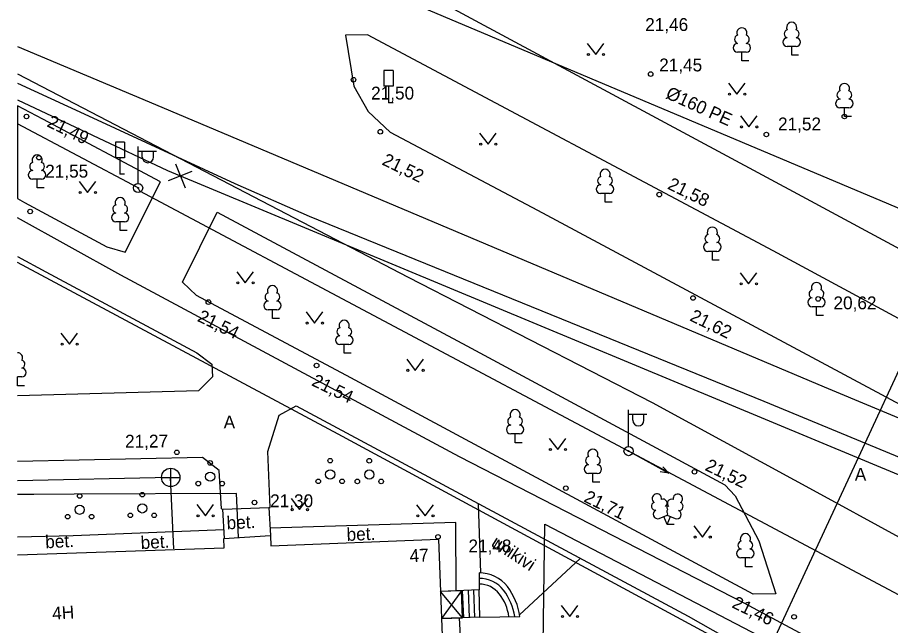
# Model space of a CAD drawing. Extents: x 714038 to 714279, y 6589845 to 6590041.
# Drawn here: x 714037.81 to 714085.35, y 6589987.55 to 6590020.65 of the extents above; entities that cross this region are included whole.
import ezdxf

# ---------------------------------------------------------------- set-up
doc = ezdxf.new("R2010")
doc.units = 0
for name, color, linetype in [('HALJASTUS', 7, 'Continuous'), ('HOONE', 7, 'Continuous'), ('HOONEDET', 7, 'Continuous'), ('KKAEV', 7, 'Continuous'), ('KORGUS', 7, 'Continuous'), ('KTRASS', 7, 'Continuous'), ('LIIKLUS', 7, 'Continuous'), ('MPKAABEL', 7, 'Continuous'), ('MPOHULIIN', 7, 'Continuous'), ('POST', 7, 'Continuous'), ('PUU', 7, 'Continuous'), ('SITRASS', 7, 'Continuous'), ('TEE', 7, 'Continuous'), ('VTRASS', 7, 'Continuous'), ('Слой 1', 7, 'Continuous')]:
    doc.layers.add(name, color=color, linetype=linetype)

msp = doc.modelspace()

# ---------------------------------------------------------------- linework, layer by layer
at = {"layer": 'HALJASTUS'}
for p, q in [((714068.837, 6590019.239), (714069.3, 6590018.632)), ((714069.3, 6590018.632), (714069.746, 6590019.239)), ((714076.527, 6590017.077), (714076.99, 6590016.47)), ((714076.99, 6590016.47), (714077.436, 6590017.077)), ((714077.18, 6590015.297), (714077.643, 6590014.691)), ((714077.643, 6590014.691), (714078.089, 6590015.297)), ((714062.973, 6590014.359), (714063.437, 6590013.753)), ((714063.437, 6590013.753), (714063.882, 6590014.359)), ((714041.166, 6590011.73), (714041.629, 6590011.124)), ((714041.629, 6590011.124), (714042.075, 6590011.73)), ((714049.75, 6590006.812), (714050.214, 6590006.205)), ((714050.214, 6590006.205), (714050.659, 6590006.812)), ((714077.159, 6590006.756), (714077.623, 6590006.149)), ((714077.623, 6590006.149), (714078.068, 6590006.756)), ((714053.525, 6590004.626), (714053.989, 6590004.019)), ((714053.989, 6590004.019), (714054.434, 6590004.626)), ((714040.176, 6590003.473), (714040.64, 6590002.866)), ((714040.64, 6590002.866), (714041.085, 6590003.473)), ((714059.008, 6590002.051), (714059.471, 6590001.444)), ((714059.471, 6590001.444), (714059.917, 6590002.051)), ((714066.767, 6589997.739), (714067.231, 6589997.132)), ((714067.231, 6589997.132), (714067.676, 6589997.739)), ((714052.711, 6589994.467), (714053.174, 6589993.861)), ((714053.174, 6589993.861), (714053.62, 6589994.467)), ((714047.581, 6589994.138), (714048.044, 6589993.531)), ((714048.044, 6589993.531), (714048.49, 6589994.138)), ((714059.548, 6589994.127), (714060.011, 6589993.52)), ((714060.011, 6589993.52), (714060.457, 6589994.127)), ((714074.646, 6589992.978), (714075.11, 6589992.371)), ((714075.11, 6589992.371), (714075.555, 6589992.978)), ((714067.421, 6589988.652), (714067.885, 6589988.046)), ((714067.885, 6589988.046), (714068.33, 6589988.652))]:
    msp.add_line(p, q, dxfattribs=at)
for centre, radius in [((714068.899, 6590018.632), 0.055), ((714069.728, 6590018.632), 0.055), ((714076.589, 6590016.47), 0.055), ((714077.418, 6590016.47), 0.055), ((714077.242, 6590014.691), 0.055), ((714078.071, 6590014.691), 0.055), ((714063.036, 6590013.753), 0.055), ((714063.864, 6590013.753), 0.055), ((714041.228, 6590011.124), 0.055), ((714042.057, 6590011.124), 0.055), ((714049.813, 6590006.205), 0.055), ((714050.642, 6590006.205), 0.055), ((714077.222, 6590006.149), 0.055), ((714078.051, 6590006.149), 0.055), ((714053.588, 6590004.019), 0.055), ((714054.416, 6590004.019), 0.055), ((714040.239, 6590002.866), 0.055), ((714041.068, 6590002.866), 0.055), ((714059.07, 6590001.444), 0.055), ((714059.899, 6590001.444), 0.055), ((714066.83, 6589997.132), 0.055), ((714067.658, 6589997.132), 0.055), ((714048.306, 6589996.404), 0.125), ((714054.839, 6589996.528), 0.125), ((714056.968, 6589996.522), 0.125), ((714048.306, 6589995.654), 0.25), ((714054.839, 6589995.778), 0.25), ((714056.968, 6589995.772), 0.25), ((714047.656, 6589995.279), 0.125), ((714048.956, 6589995.279), 0.125), ((714054.189, 6589995.403), 0.125), ((714055.489, 6589995.403), 0.125), ((714056.318, 6589995.397), 0.125), ((714057.618, 6589995.397), 0.125), ((714044.607, 6589994.679), 0.125), ((714041.196, 6589994.606), 0.125), ((714041.196, 6589993.856), 0.25), ((714044.607, 6589993.929), 0.25), ((714052.773, 6589993.861), 0.055), ((714053.602, 6589993.861), 0.055), ((714040.546, 6589993.481), 0.125), ((714041.846, 6589993.481), 0.125), ((714043.957, 6589993.554), 0.125), ((714045.257, 6589993.554), 0.125), ((714047.643, 6589993.531), 0.055), ((714048.472, 6589993.531), 0.055), ((714059.61, 6589993.52), 0.055), ((714060.439, 6589993.52), 0.055), ((714074.709, 6589992.371), 0.055), ((714075.538, 6589992.371), 0.055), ((714067.484, 6589988.046), 0.055), ((714068.312, 6589988.046), 0.055)]:
    msp.add_circle(centre, radius, dxfattribs=at)
at = {"layer": 'HOONE'}
for points in [[(714037.81, 6590017.576), (714059.08, 6590006.51), (714072.38, 6589999.69), (714082.14, 6589994.37), (714104.85, 6589981.96), (714150.21, 6589957.43), (714183.55, 6589939.45), (714202.68, 6589928.99), (714214.04, 6589922.75), (714222.92, 6589918.06), (714237.47, 6589910.29), (714252.27, 6589902.23), (714256.602, 6589899.815), (714258.577, 6589898.715), (714261.69, 6589896.98)], [(714049.84, 6589992.36), (714049.74, 6589994.74), (714040.901, 6589994.702), (714038.703, 6589994.692), (714037.81, 6589994.688)], [(714049.068, 6589991.791), (714049.048, 6589992.294), (714051.589, 6589992.446), (714051.611, 6589991.89), (714060.739, 6589992.247), (714061.143, 6589981.755), (714037.81, 6589980.739)], [(714037.81, 6589991.404), (714049.068, 6589991.791)], [(714060.905, 6589987.935), (714062.038, 6589987.979), (714061.984, 6589989.451), (714060.848, 6589989.407)], [(714062.038, 6589987.979), (714060.848, 6589989.407)], [(714061.984, 6589989.451), (714060.905, 6589987.935)]]:
    msp.add_lwpolyline(points, dxfattribs=at)
at = {"layer": 'HOONEDET'}
for p, q in [((714062.946, 6589990.419), (714062.947, 6589989.494)), ((714062.947, 6589989.494), (714060.848, 6589989.413)), ((714062.035, 6589989.459), (714062.092, 6589987.975)), ((714062.353, 6589989.471), (714062.411, 6589987.988)), ((714062.638, 6589989.482), (714062.696, 6589987.999)), ((714062.993, 6589988.01), (714062.947, 6589989.494)), ((714062.993, 6589988.01), (714060.905, 6589987.93)), ((714062.993, 6589988.01), (714065.167, 6589988.045))]:
    msp.add_line(p, q, dxfattribs=at)
for points in [[(714037.81, 6589992.387), (714040.847, 6589992.447), (714049.055, 6589992.781)], [(714061.859, 6589987.966), (714062.226, 6589981.203), (714052.13, 6589980.7)]]:
    msp.add_lwpolyline(points, dxfattribs=at)
for centre, radius, start, end in [((714062.981, 6589988.523), 1.897, 37.2498, 91.0776), ((714062.991, 6589988.505), 1.615, 36.7967, 91.5949), ((714062.943, 6589988.406), 1.409, 37.7811, 89.8581), ((714061.728, 6589987.57), 3.472, 7.8652, 37.2498), ((714062.053, 6589987.716), 2.536, 7.2366, 37.7811), ((714061.703, 6589987.542), 3.223, 8.8928, 36.7967)]:
    msp.add_arc(centre, radius, start, end, dxfattribs=at)
at = {"layer": 'KKAEV'}
for p, q in [((714046.154, 6589995.114), (714046.154, 6589996.114)), ((714045.654, 6589995.614), (714046.654, 6589995.614))]:
    msp.add_line(p, q, dxfattribs=at)
msp.add_circle((714046.154, 6589995.614), 0.5, dxfattribs=at)
at = {"layer": 'KORGUS'}
for centre in [(714072.29, 6590017.57), (714056.11, 6590017.26), (714038.3, 6590015.26), (714082.84, 6590015.26), (714057.57, 6590014.43), (714078.59, 6590014.28), (714038.98, 6590013.02), (714072.76, 6590011.01), (714038.5, 6590010.09), (714048.21, 6590005.16), (714074.6, 6590005.38), (714081.41, 6590005.33), (714054.1, 6590001.71), (714046.49, 6589996.98), (714074.68, 6589995.92), (714067.67, 6589995.03), (714050.72, 6589994.25), (714060.71, 6589992.38), (714080.1, 6589988.03)]:
    msp.add_circle(centre, 0.125, dxfattribs=at)
at = {"layer": 'KTRASS'}
for points in [[(714108.526, 6590000.746), (714093.581, 6590006.995), (714058.132, 6590021.931)], [(714046.149, 6589995.611), (714037.81, 6589995.433)], [(714046.319, 6589991.733), (714046.149, 6589995.611)]]:
    msp.add_lwpolyline(points, dxfattribs=at)
at = {"layer": 'LIIKLUS'}
for points in [[(714057.768, 6590017.762), (714057.768, 6590016.912)], [(714058.268, 6590017.762), (714057.768, 6590017.762)], [(714058.268, 6590017.762), (714058.268, 6590016.912)], [(714058.268, 6590016.912), (714057.768, 6590016.912)], [(714058.018, 6590016.912), (714058.018, 6590016.012)], [(714058.268, 6590016.012), (714058.018, 6590016.012)], [(714043.141, 6590013.869), (714043.141, 6590013.019)], [(714043.641, 6590013.869), (714043.141, 6590013.869)], [(714043.641, 6590013.869), (714043.641, 6590013.019)], [(714043.641, 6590013.019), (714043.141, 6590013.019)], [(714043.391, 6590013.019), (714043.391, 6590012.119)], [(714043.641, 6590012.119), (714043.391, 6590012.119)]]:
    msp.add_lwpolyline(points, dxfattribs=at)
at = {"layer": 'MPKAABEL'}
for p, q in [((714046.422, 6590012.681), (714046.935, 6590011.378)), ((714046.028, 6590011.773), (714047.33, 6590012.286))]:
    msp.add_line(p, q, dxfattribs=at)
for points in [[(714037.81, 6590016.164), (714045.98, 6590012.32), (714093.89, 6589992.4), (714122, 6589980.75)], [(714044.379, 6590011.372), (714037.81, 6590014.854)], [(714071.088, 6589997.05), (714044.469, 6590011.202), (714044.379, 6590011.372)], [(714097.447, 6589982.821), (714094.758, 6589984.46), (714071.268, 6589996.96), (714071.088, 6589997.05)]]:
    msp.add_lwpolyline(points, dxfattribs=at)
at = {"layer": 'MPOHULIIN'}
for p, q in [((714071.307, 6589996.929), (714073.275, 6589995.839)), ((714073.275, 6589995.839), (714072.953, 6589996.189)), ((714073.275, 6589995.839), (714072.808, 6589995.928))]:
    msp.add_line(p, q, dxfattribs=at)
at = {"layer": 'POST'}
for p, q in [((714044.379, 6590011.622), (714044.379, 6590013.622)), ((714044.379, 6590013.372), (714045.379, 6590013.372)), ((714044.606, 6590013.051), (714044.606, 6590013.372)), ((714045.218, 6590013.051), (714045.218, 6590013.372)), ((714071.088, 6589997.3), (714071.088, 6589999.3)), ((714071.088, 6589999.05), (714072.088, 6589999.05)), ((714071.315, 6589998.729), (714071.315, 6589999.05)), ((714071.928, 6589998.729), (714071.928, 6589999.05))]:
    msp.add_line(p, q, dxfattribs=at)
for centre, radius in [((714044.379, 6590011.372), 0.25), ((714044.379, 6590011.372), 0.0234), ((714071.088, 6589997.05), 0.25), ((714071.088, 6589997.05), 0.0234)]:
    msp.add_circle(centre, radius, dxfattribs=at)
for centre in [(714044.912, 6590013.051), (714071.622, 6589998.729)]:
    msp.add_arc(centre, 0.306, 180, 0, dxfattribs=at)
at = {"layer": 'PUU'}
for p, q in [((714080.21, 6590019.065), (714079.73, 6590019.065)), ((714079.97, 6590018.59), (714079.97, 6590019.065)), ((714077.5, 6590018.765), (714077.02, 6590018.765)), ((714077.26, 6590018.29), (714077.26, 6590018.765)), ((714080.35, 6590018.59), (714079.97, 6590018.59)), ((714077.64, 6590018.29), (714077.26, 6590018.29)), ((714083.08, 6590015.735), (714082.6, 6590015.735)), ((714082.84, 6590015.26), (714082.84, 6590015.735)), ((714083.22, 6590015.26), (714082.84, 6590015.26)), ((714039.118, 6590011.844), (714038.638, 6590011.844)), ((714038.878, 6590011.369), (714038.878, 6590011.844)), ((714039.258, 6590011.369), (714038.878, 6590011.369)), ((714070.048, 6590011.068), (714069.568, 6590011.068)), ((714069.808, 6590010.593), (714069.808, 6590011.068)), ((714070.188, 6590010.593), (714069.808, 6590010.593)), ((714043.644, 6590009.525), (714043.164, 6590009.525)), ((714043.404, 6590009.05), (714043.404, 6590009.525)), ((714043.784, 6590009.05), (714043.404, 6590009.05)), ((714075.89, 6590007.921), (714075.41, 6590007.921)), ((714075.65, 6590007.446), (714075.65, 6590007.921)), ((714076.03, 6590007.446), (714075.65, 6590007.446)), ((714081.561, 6590004.909), (714081.081, 6590004.909)), ((714081.321, 6590004.434), (714081.321, 6590004.909)), ((714051.935, 6590004.735), (714051.455, 6590004.735)), ((714051.695, 6590004.26), (714051.695, 6590004.735)), ((714081.701, 6590004.434), (714081.321, 6590004.434)), ((714052.075, 6590004.26), (714051.695, 6590004.26)), ((714055.847, 6590002.847), (714055.367, 6590002.847)), ((714055.607, 6590002.372), (714055.607, 6590002.847)), ((714055.987, 6590002.372), (714055.607, 6590002.372)), ((714037.81, 6590000.609), (714037.81, 6590001.084)), ((714038.05, 6590001.084), (714037.81, 6590001.084)), ((714038.19, 6590000.609), (714037.81, 6590000.609)), ((714065.148, 6589997.982), (714064.668, 6589997.982)), ((714064.908, 6589997.507), (714064.908, 6589997.982)), ((714065.288, 6589997.507), (714064.908, 6589997.507)), ((714069.386, 6589995.83), (714068.906, 6589995.83)), ((714069.146, 6589995.355), (714069.146, 6589995.83)), ((714069.526, 6589995.355), (714069.146, 6589995.355)), ((714072.748, 6589993.384), (714073.193, 6589993.559)), ((714073.188, 6589993.049), (714073.013, 6589993.489)), ((714073.188, 6589993.049), (714073.368, 6589993.489)), ((714073.193, 6589993.559), (714073.633, 6589993.379)), ((714073.568, 6589993.049), (714073.188, 6589993.049)), ((714077.688, 6589991.233), (714077.208, 6589991.233)), ((714077.448, 6589990.758), (714077.448, 6589991.233)), ((714077.828, 6589990.758), (714077.448, 6589990.758))]:
    msp.add_line(p, q, dxfattribs=at)
msp.add_lwpolyline([(714073.193, 6589994.054), (714073.173, 6589993.979), (714073.173, 6589993.959), (714073.183, 6589993.929), (714073.203, 6589993.894), (714073.208, 6589993.874), (714073.193, 6589993.839), (714073.168, 6589993.789), (714073.163, 6589993.764), (714073.168, 6589993.749), (714073.178, 6589993.719), (714073.213, 6589993.659), (714073.218, 6589993.639), (714073.213, 6589993.619), (714073.198, 6589993.584), (714073.193, 6589993.559)], dxfattribs=at)
for centre, radius, start, end in [((714077.26, 6590019.81), 0.277, 332.5799, 207.4201), ((714079.8, 6590019.763), 0.233, 109.0217, 253.1415), ((714079.97, 6590020.11), 0.277, 332.5799, 207.4201), ((714080.14, 6590019.763), 0.233, 286.8508, 70.9859), ((714077.09, 6590019.463), 0.233, 109.0217, 253.1415), ((714077.43, 6590019.463), 0.233, 286.8508, 70.9859), ((714079.733, 6590019.302), 0.238, 90.0016, 269.3953), ((714080.207, 6590019.302), 0.238, 270.6047, 89.9984), ((714077.023, 6590019.002), 0.238, 90.0016, 269.3953), ((714077.497, 6590019.002), 0.238, 270.6047, 89.9984), ((714082.67, 6590016.433), 0.233, 109.0217, 253.1415), ((714082.84, 6590016.78), 0.277, 332.5799, 207.4201), ((714083.01, 6590016.433), 0.233, 286.8508, 70.9859), ((714082.603, 6590015.972), 0.238, 90.0016, 269.3953), ((714083.077, 6590015.972), 0.238, 270.6047, 89.9984), ((714038.878, 6590012.889), 0.277, 332.5799, 207.4201), ((714038.708, 6590012.542), 0.233, 109.0217, 253.1415), ((714039.048, 6590012.542), 0.233, 286.8508, 70.9859), ((714069.808, 6590012.113), 0.277, 332.5799, 207.4201), ((714038.64, 6590012.082), 0.238, 90.0016, 269.3953), ((714039.115, 6590012.082), 0.238, 270.6047, 89.9984), ((714069.638, 6590011.765), 0.233, 109.0217, 253.1415), ((714069.978, 6590011.765), 0.233, 286.8508, 70.9859), ((714069.57, 6590011.305), 0.238, 90.0016, 269.3953), ((714070.045, 6590011.305), 0.238, 270.6047, 89.9984), ((714043.404, 6590010.57), 0.277, 332.5799, 207.4201), ((714043.167, 6590009.762), 0.238, 90.0016, 269.3953), ((714043.234, 6590010.222), 0.233, 109.0217, 253.1415), ((714043.574, 6590010.222), 0.233, 286.8508, 70.9859), ((714043.642, 6590009.762), 0.238, 270.6047, 89.9984), ((714075.65, 6590008.966), 0.277, 332.5799, 207.4201), ((714075.48, 6590008.618), 0.233, 109.0217, 253.1415), ((714075.82, 6590008.618), 0.233, 286.8508, 70.9859), ((714075.413, 6590008.158), 0.238, 90.0016, 269.3953), ((714075.888, 6590008.158), 0.238, 270.6047, 89.9984), ((714081.321, 6590005.954), 0.277, 332.5799, 207.4201), ((714051.695, 6590005.78), 0.277, 332.5799, 207.4201), ((714081.151, 6590005.607), 0.233, 109.0217, 253.1415), ((714081.491, 6590005.607), 0.233, 286.8508, 70.9859), ((714051.525, 6590005.432), 0.233, 109.0217, 253.1415), ((714051.865, 6590005.432), 0.233, 286.8508, 70.9859), ((714081.083, 6590005.146), 0.238, 90.0016, 269.3953), ((714081.558, 6590005.146), 0.238, 270.6047, 89.9984), ((714051.458, 6590004.972), 0.238, 90.0016, 269.3953), ((714051.933, 6590004.972), 0.238, 270.6047, 89.9984), ((714055.607, 6590003.892), 0.277, 332.5799, 207.4201), ((714055.37, 6590003.085), 0.238, 90.0016, 269.3953), ((714055.437, 6590003.545), 0.233, 109.0217, 253.1415), ((714055.777, 6590003.545), 0.233, 286.8508, 70.9859), ((714055.845, 6590003.085), 0.238, 270.6047, 89.9984), ((714037.81, 6590002.129), 0.277, 332.5799, 90.0302), ((714037.981, 6590001.781), 0.233, 286.8508, 70.9859), ((714038.048, 6590001.321), 0.238, 270.6047, 89.9984), ((714064.908, 6589999.027), 0.277, 332.5799, 207.4201), ((714064.738, 6589998.68), 0.233, 109.0217, 253.1415), ((714065.078, 6589998.68), 0.233, 286.8508, 70.9859), ((714064.67, 6589998.22), 0.238, 90.0016, 269.3953), ((714065.145, 6589998.22), 0.238, 270.6047, 89.9984), ((714069.146, 6589996.875), 0.277, 332.5799, 207.4201), ((714068.976, 6589996.528), 0.233, 109.0217, 253.1415), ((714069.316, 6589996.528), 0.233, 286.8508, 70.9859), ((714068.909, 6589996.067), 0.238, 90.0016, 269.3953), ((714069.384, 6589996.067), 0.238, 270.6047, 89.9984), ((714072.631, 6589994.463), 0.256, 111.5027, 232.5173), ((714072.631, 6589994.463), 0.256, 350.4856, 111.5002), ((714072.965, 6589994.212), 0.224, 308.5041, 111.5725), ((714073.428, 6589994.208), 0.225, 67.7016, 230.5126), ((714073.767, 6589994.454), 0.256, 67.6168, 188.6314), ((714073.767, 6589994.454), 0.256, 306.5997, 67.6143), ((714072.557, 6589994.051), 0.224, 111.4304, 274.4987), ((714072.661, 6589993.607), 0.237, 111.5014, 291.5004), ((714073.192, 6589993.816), 0.237, 66.7655, 111.5015), ((714073.723, 6589993.599), 0.237, 247.6166, 67.6155), ((714073.834, 6589994.042), 0.224, 264.6183, 67.6866), ((714077.448, 6589992.278), 0.277, 332.5799, 207.4201), ((714077.278, 6589991.931), 0.233, 109.0217, 253.1415), ((714077.618, 6589991.931), 0.233, 286.8508, 70.9859), ((714077.211, 6589991.471), 0.238, 90.0016, 269.3953), ((714077.686, 6589991.471), 0.238, 270.6047, 89.9984)]:
    msp.add_arc(centre, radius, start, end, dxfattribs=at)
at = {"layer": 'SITRASS'}
for points in [[(714078.609, 6589985.937), (714086.299, 6590002.484), (714089.168, 6590008.661), (714094.05, 6590020), (714095.092, 6590022.185), (714097.899, 6590028.624), (714100.251, 6590033.606)], [(714037.81, 6590017.083), (714041.45, 6590015.4), (714049.64, 6590011.61), (714053.69, 6590009.84), (714078.46, 6589999.77), (714120.53, 6589982.37), (714120.99, 6589982.37), (714121.09, 6589982.42), (714121.19, 6589982.57), (714121.29, 6589982.87), (714121.49, 6589988.215), (714121.85, 6589997.82), (714121.9, 6589998.22), (714123.574, 6590001.009)], [(714077.958, 6589985.72), (714077.539, 6589985.944), (714055.281, 6589997.97), (714037.81, 6590007.322)]]:
    msp.add_lwpolyline(points, dxfattribs=at)
at = {"layer": 'TEE'}
for p, q in [((714037.81, 6590015.847), (714037.81, 6590010.794)), ((714039.185, 6590015.114), (714037.81, 6590015.847)), ((714045.595, 6590011.7), (714039.185, 6590015.114)), ((714043.669, 6590007.874), (714045.595, 6590011.7)), ((714037.81, 6590010.794), (714038.198, 6590010.582)), ((714038.198, 6590010.582), (714042.668, 6590008.167)), ((714042.668, 6590008.167), (714043.669, 6590007.874))]:
    msp.add_line(p, q, dxfattribs=at)
for points in [[(714056.466, 6590027.31), (714056.476, 6590024.886), (714056.788, 6590023.888), (714058.417, 6590022.828), (714080.514, 6590010.928), (714103.015, 6589998.807), (714111.415, 6589994.157), (714112.824, 6589994.218)], [(714037.81, 6590007.64), (714039.362, 6590006.808), (714047.582, 6590002.402), (714048.393, 6590001.776), (714048.44, 6590001.088), (714047.676, 6590000.322), (714037.81, 6590000.057)], [(714051.575, 6589993.973), (714051.436, 6589997.034), (714052.061, 6589999.007), (714052.983, 6589999.515), (714074.327, 6589988.058), (714079.586, 6589985.085), (714080.323, 6589984.396)], [(714048.922, 6589993.908), (714048.79, 6589996), (714047.885, 6589996.695), (714037.81, 6589996.474)], [(714048.922, 6589993.908), (714048.989, 6589993.881)], [(714049.084, 6589992.296), (714048.989, 6589993.881), (714051.494, 6589993.985), (714051.585, 6589992.446)], [(714051.494, 6589993.985), (714051.575, 6589993.973)], [(714063.04, 6589990.419), (714062.915, 6589994.183)], [(714061.701, 6589989.446), (714061.689, 6589993.155), (714051.562, 6589992.845)], [(714068.452, 6589991.211), (714065.152, 6589988.144)]]:
    msp.add_lwpolyline(points, dxfattribs=at)
for points in [[(714111.749, 6589987.81), (714112.752, 6589989.647), (714101.456, 6589995.811), (714078.958, 6590007.942), (714056.863, 6590019.705), (714055.67, 6590019.684), (714056.126, 6590016.909), (714056.904, 6590015.524), (714058.111, 6590014.408), (714066.132, 6590010.156), (714094.483, 6589994.979), (714109.175, 6589987.135), (714110.128, 6589986.933), (714111.028, 6589987.18)], [(714046.799, 6590006.241), (714048.688, 6590010.05), (714062.282, 6590002.782), (714076.323, 6589995.207), (714076.884, 6589994.614), (714078.173, 6589992.169), (714079.099, 6589989.279), (714077.881, 6589989.263), (714055.959, 6590001.029), (714047.565, 6590005.514)]]:
    msp.add_lwpolyline(points, close=True, dxfattribs=at)
at = {"layer": 'VTRASS'}
for points in [[(714037.81, 6590019.066), (714045.328, 6590015.922), (714081.738, 6590000.542), (714101.803, 6589992.176)], [(714153.798, 6589949.498), (714152.517, 6589948.338), (714134.349, 6589958.294), (714134.144, 6589958.409), (714120.209, 6589965.86), (714104.085, 6589974.529), (714097.438, 6589978.146), (714096.95, 6589978.424), (714085.013, 6589984.641), (714084.705, 6589984.858), (714077.379, 6589988.763), (714061.877, 6589996.73), (714043.432, 6590006.628), (714037.81, 6590009.751)]]:
    msp.add_lwpolyline(points, dxfattribs=at)
at = {"layer": 'Слой 1'}
msp.add_lwpolyline([(714064.59, 6589902.42), (714061.29, 6589975.82), (714066.29, 6589976.05), (714066.53, 6589993.08), (714086, 6589982.93), (714087.46, 6589939.06), (714088.9, 6589899.98), (714072.76, 6589898.26)], close=True, dxfattribs=at)

# ---------------------------------------------------------------- texts
at = {"layer": 'HOONE'}
for s, rotation, p in [('47', 2.582, (714059.18, 6589991)), ('4H', 3.5967, (714039.725, 6589987.864))]:
    msp.add_text(s, height=0.7, rotation=rotation, dxfattribs=at).set_placement(p)
at = {"layer": 'HOONEDET'}
for rotation, p in [(2.7672, (714049.216, 6589992.788)), (2.252, (714055.746, 6589992.159)), (3.0906, (714044.537, 6589991.712))]:
    msp.add_text('bet.', height=0.7, rotation=rotation, dxfattribs=at).set_placement(p)
at = {"layer": 'KORGUS'}
for s, p in [('21,46', (714071.993, 6590019.915)), ('21,45', (714072.756, 6590017.715)), ('21,50', (714057.069, 6590016.185)), ('21,52', (714079.226, 6590014.505)), ('21,55', (714039.321, 6590011.935)), ('20,62', (714082.246, 6590004.765)), ('21,30', (714051.569, 6589993.995)), ('21,48', (714062.369, 6589991.535))]:
    msp.add_text(s, height=0.7, dxfattribs=at).set_placement(p)
for s, rotation, p in [('21,49', 334.0139, (714039.369, 6590014.741)), ('21,52', 334.0139, (714057.615, 6590012.664)), ('21,58', 334.0139, (714073.161, 6590011.346)), ('21,54', 334.0139, (714047.558, 6590004.147)), ('21,62', 334.0139, (714074.375, 6590004.174)), ('21,54', 334.0139, (714053.778, 6590000.647)), ('21,27', 0.276, (714043.671, 6589997.236)), ('21,52', 334.0139, (714075.205, 6589996.034)), ('21,71', 334.0139, (714068.601, 6589994.321)), ('21,46', 334.0139, (714076.663, 6589988.56))]:
    msp.add_text(s, height=0.7, rotation=rotation, dxfattribs=at).set_placement(p)
at = {"layer": 'KTRASS'}
msp.add_text('%%c160 PE', height=0.7, rotation=335.6802, dxfattribs=at).set_placement((714073.061, 6590016.284))
at = {"layer": 'TEE'}
for p in [(714049.039, 6589998.28), (714083.408, 6589995.437)]:
    msp.add_text('A', height=0.7, dxfattribs=at).set_placement(p)
for s, rotation, p in [('bet.', 2.7396, (714039.337, 6589991.758)), ('unikivi', 326.7121, (714063.551, 6589991.916))]:
    msp.add_text(s, height=0.7, rotation=rotation, dxfattribs=at).set_placement(p)

doc.saveas('drawing.dxf')
